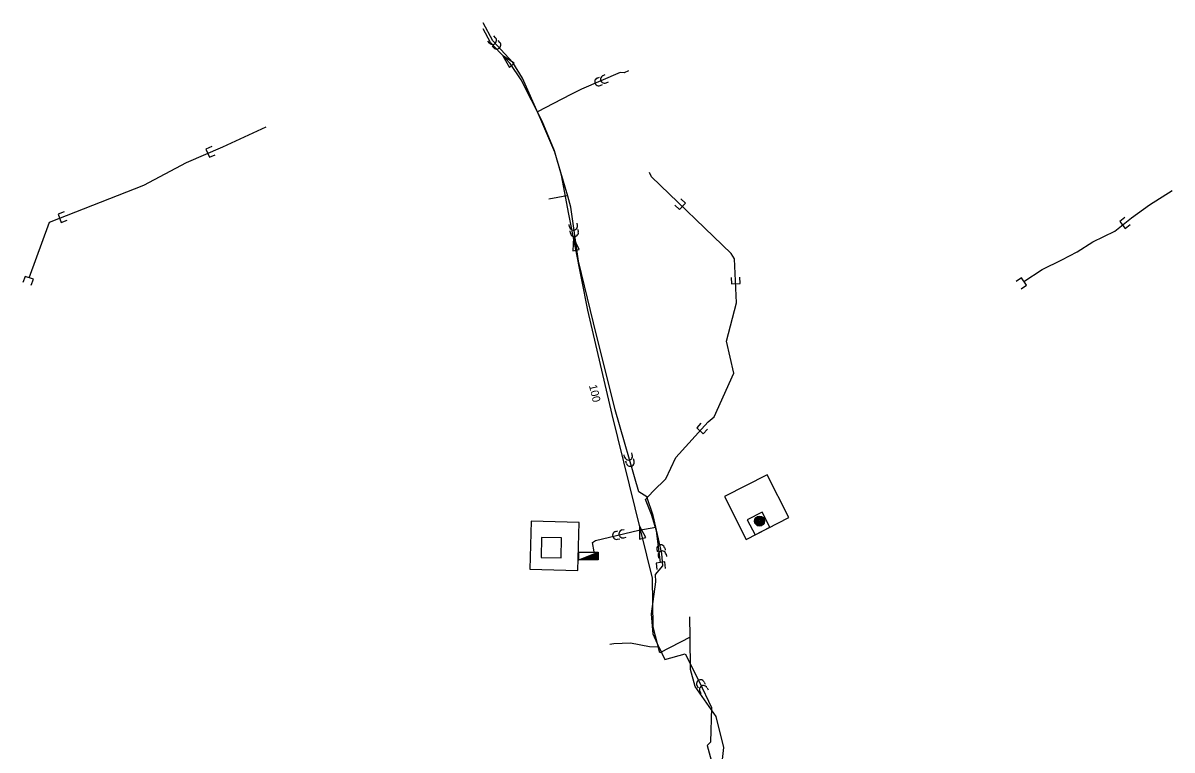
# Model space of a CAD drawing. Extents: x -545007 to -535309, y -1042871 to -1037511.
# Drawn here: x -543287 to -541851, y -1038419 to -1037511 of the extents above; entities that cross this region are included whole.
import ezdxf

# ---------------------------------------------------------------- set-up
doc = ezdxf.new("R2010")
doc.units = 0
for name, color, linetype in [('Vrstva 3', 7, 'Continuous'), ('Vrstva 32', 7, 'Continuous'), ('Vrstva 33', 7, 'Continuous'), ('Vrstva 41', 7, 'Continuous'), ('Vrstva 55', 7, 'Continuous'), ('Vrstva 56', 7, 'Continuous'), ('Vrstva 7', 7, 'Continuous')]:
    doc.layers.add(name, color=color, linetype=linetype)

msp = doc.modelspace()

# ---------------------------------------------------------------- linework, layer by layer
at = {"layer": 'Vrstva 3'}
for points in [[(-542623, -1037670.9), (-542638.2, -1037633.8), (-542664.4, -1037582.1), (-542678.2, -1037561.9), (-542702.7, -1037535.4), (-542712, -1037518.4)], [(-542417.5, -1038472.3), (-542411.5, -1038415.7), (-542420.7, -1038377.1), (-542447.3, -1038339.5), (-542452.8, -1038318.4), (-542453.3, -1038278), (-542491.3, -1038297.4), (-542499.5, -1038265.3), (-542500.4, -1038204.1), (-542550.8, -1037999.9), (-542581.1, -1037869.8), (-542604.9, -1037749.8), (-542614.1, -1037701.3), (-542623, -1037670.9)], [(-542453.3, -1038278), (-542453.7, -1038252.5)]]:
    msp.add_lwpolyline(points, dxfattribs=at)
for points in [[(-542679.2, -1037566.6), (-542673.4, -1037561.2), (-542687.2, -1037552.1)], [(-542599.9, -1037795.5), (-542592.1, -1037793.9), (-542599.1, -1037779)], [(-542516.6, -1038155.4), (-542508.8, -1038153.5), (-542516.5, -1038138.9)]]:
    msp.add_lwpolyline(points, close=True, dxfattribs=at)
at = {"layer": 'Vrstva 32'}
for p, q in [((-542704, -1037536.3), (-542706, -1037534.1)), ((-542696.6, -1037529.6), (-542698.6, -1037527.4)), ((-542691.2, -1037535.4), (-542693.2, -1037533.2)), ((-542698.5, -1037542.2), (-542700.6, -1037540)), ((-542562.2, -1037576.8), (-542559.5, -1037575.6)), ((-542569.6, -1037580), (-542566.8, -1037578.8)), ((-542565.6, -1037589.2), (-542562.9, -1037588)), ((-542558.3, -1037586), (-542555.5, -1037584.8)), ((-542607.4, -1037726.8), (-542629.9, -1037731.1)), ((-542604, -1037765.5), (-542604.4, -1037762.6)), ((-542594.1, -1037764.1), (-542594.5, -1037761.2)), ((-542602.9, -1037773.5), (-542603.3, -1037770.5)), ((-542593, -1037772.1), (-542593.4, -1037769.1)), ((-542535.2, -1038053.3), (-542536, -1038050.4)), ((-542525.6, -1038050.5), (-542526.4, -1038047.7)), ((-542533, -1038061), (-542533.8, -1038058.1)), ((-542523.4, -1038058.2), (-542524.2, -1038055.3)), ((-542546.4, -1038146), (-542543.5, -1038145.3)), ((-542538.6, -1038144.1), (-542535.7, -1038143.5)), ((-542544.1, -1038155.7), (-542541.1, -1038155)), ((-542536.3, -1038153.9), (-542533.4, -1038153.2)), ((-542485.2, -1038166.4), (-542484.6, -1038169.3)), ((-542495, -1038168.6), (-542494.3, -1038171.5)), ((-542493.3, -1038176.4), (-542492.6, -1038179.3)), ((-542483.5, -1038174.2), (-542482.8, -1038177.1)), ((-542444.9, -1038338.4), (-542443.5, -1038341.1)), ((-542436, -1038333.9), (-542434.6, -1038336.5)), ((-542441.2, -1038345.5), (-542439.9, -1038348.2)), ((-542432.3, -1038341), (-542431, -1038343.7))]:
    msp.add_line(p, q, dxfattribs=at)
for points in [[(-542492.6, -1038290), (-542499.4, -1038274.3), (-542501.8, -1038248.7), (-542496.1, -1038209), (-542496.8, -1038199.7), (-542487.4, -1038188.9), (-542488.8, -1038173.3), (-542499.4, -1038125.9), (-542507.4, -1038102.6), (-542517.5, -1038096.7), (-542547, -1037994.2), (-542574.2, -1037885.6), (-542592.9, -1037808.7), (-542602.4, -1037741), (-542606, -1037727.3), (-542622.2, -1037672.3), (-542639.7, -1037631.6), (-542662.7, -1037580.3), (-542674.8, -1037560.6), (-542699.7, -1037533.6), (-542712, -1037511.2)], [(-542530.2, -1037571.1), (-542535.7, -1037573.3), (-542540.6, -1037573), (-542589.2, -1037593.8), (-542602.3, -1037600.4), (-542624.1, -1037611.8), (-542644, -1037622)], [(-542573.1, -1038171.3), (-542575.2, -1038159.8), (-542571.4, -1038157.1), (-542517.4, -1038144.3), (-542496.2, -1038140.4)], [(-542553.9, -1038286.7), (-542548.8, -1038285.7), (-542528, -1038285), (-542504.1, -1038289.5), (-542492.6, -1038290)], [(-542492.6, -1038290), (-542485.1, -1038305.8), (-542459.5, -1038298.6), (-542442, -1038333.1), (-542426.8, -1038365.6), (-542428.1, -1038408.8), (-542432.3, -1038413.3), (-542412.6, -1038485.1)]]:
    msp.add_lwpolyline(points, dxfattribs=at)
for centre, start, end in [((-542700.3, -1037533), 222.6962, 42.6972), ((-542694.9, -1037538.8), 222.6962, 42.6972), ((-542560.3, -1037581.4), 113.2484, 293.2495), ((-542567.6, -1037584.6), 113.2484, 293.2495), ((-542599.1, -1037764.8), 188.0116, 8.0127), ((-542598, -1037772.8), 188.0116, 8.0127), ((-542530.4, -1038051.9), 196.0671, 16.0682), ((-542528.2, -1038059.6), 196.0671, 16.0682), ((-542545.2, -1038150.9), 103.338, 283.3391), ((-542537.4, -1038149), 103.338, 283.3391), ((-542490.1, -1038167.5), 12.5467, 192.5478), ((-542488.4, -1038175.3), 12.5467, 192.5478), ((-542440.4, -1038336.1), 26.975, 206.976), ((-542436.8, -1038343.3), 26.975, 206.976)]:
    msp.add_arc(centre, 5, start, end, dxfattribs=at)
at = {"layer": 'Vrstva 33'}
for points in [[(-543278.9, -1037829.4), (-543253.7, -1037760), (-543135.6, -1037713.5), (-543082.5, -1037685.2), (-543037.3, -1037665.8), (-542982.8, -1037640.7)], [(-543050.9, -1037665.6), (-543058.2, -1037668.8), (-543053.9, -1037678.9), (-543046.5, -1037675.8)], [(-542490.4, -1038184.7), (-542495.3, -1038145.1), (-542501.8, -1038124.8), (-542509.2, -1038106.1), (-542499.6, -1038095.7), (-542483.7, -1038080.1), (-542471.1, -1038053.6), (-542430.9, -1038009.1), (-542423.3, -1038002.8), (-542398.8, -1037948.4), (-542408, -1037908.2), (-542395.3, -1037860.7), (-542397.8, -1037805.5), (-542402.1, -1037799.1), (-542501.5, -1037703.1), (-542504.1, -1037697.9)], [(-542036.5, -1037834.1), (-542013.8, -1037818.8), (-541989, -1037806.7), (-541970.1, -1037797), (-541950.2, -1037784.6), (-541923, -1037770.9), (-541902.1, -1037754.5), (-541879.7, -1037738.3), (-541851.4, -1037720.2)], [(-542472.6, -1037738.7), (-542466.8, -1037744.2), (-542459.2, -1037736.3), (-542465, -1037730.8)], [(-543235.5, -1037746.9), (-543242.9, -1037749.9), (-543238.9, -1037760.1), (-543231.4, -1037757.2)], [(-541910.4, -1037754), (-541916.7, -1037759), (-541909.9, -1037767.6), (-541903.6, -1037762.7)], [(-543276.4, -1037838.7), (-543273.7, -1037831.2), (-543284, -1037827.5), (-543286.8, -1037835)], [(-542402.2, -1037829), (-542401.9, -1037837), (-542390.9, -1037836.5), (-542391.2, -1037828.5)], [(-542040, -1037843.1), (-542033.4, -1037838.6), (-542039.5, -1037829.5), (-542046.2, -1037834)], [(-542439.9, -1038010.8), (-542445.2, -1038016.7), (-542437.1, -1038024.1), (-542431.7, -1038018.1)], [(-542484, -1038192), (-542485, -1038184), (-542495.9, -1038185.4), (-542494.9, -1038193.3)]]:
    msp.add_lwpolyline(points, dxfattribs=at)
at = {"layer": 'Vrstva 41'}
msp.add_lwpolyline([(-542592.6, -1038181.5), (-542592.6, -1038171.9), (-542568.3, -1038171.9)], dxfattribs=at)
for points in [[(-542568.3, -1038171.9), (-542568.3, -1038181.5), (-542592.6, -1038181.5)], [(-542568.9, -1038172.9), (-542568.9, -1038180.9), (-542589.2, -1038180.9)], [(-542569.6, -1038173.8), (-542569.6, -1038180.2), (-542585.9, -1038180.2)], [(-542570.2, -1038174.7), (-542570.2, -1038179.6), (-542582.5, -1038179.6)], [(-542570.8, -1038175.7), (-542570.8, -1038179), (-542579.1, -1038179)], [(-542571.5, -1038176.6), (-542571.5, -1038178.3), (-542575.8, -1038178.3)]]:
    msp.add_lwpolyline(points, close=True, dxfattribs=at)
at = {"layer": 'Vrstva 55'}
for points in [[(-542372.3, -1038150.2), (-542353.8, -1038140.4), (-542363.6, -1038121.8), (-542382.1, -1038131.6), (-542372.3, -1038150.2)], [(-542614.5, -1038178.9), (-542614, -1038153.9), (-542639, -1038153.4), (-542639.5, -1038178.4), (-542614.5, -1038178.9)]]:
    msp.add_lwpolyline(points, dxfattribs=at)
at = {"layer": 'Vrstva 56'}
for points in [[(-542383.4, -1038155.8), (-542329.9, -1038128.6), (-542357.1, -1038075.1), (-542410.6, -1038102.3), (-542383.4, -1038155.8)], [(-542593.8, -1038194.8), (-542592.1, -1038134.8), (-542652.1, -1038133.1), (-542653.8, -1038193.1), (-542593.8, -1038194.8)]]:
    msp.add_lwpolyline(points, dxfattribs=at)
at = {"layer": 'Vrstva 7'}
for radius in [6.3, 5.3, 4.3, 3.3, 2.3, 1.3, 0.3]:
    msp.add_circle((-542366.6, -1038133), radius, dxfattribs=at)

# ---------------------------------------------------------------- texts
at = {"layer": 'Vrstva 3'}
msp.add_text('100', height=10, rotation=283.0891, dxfattribs=at).set_placement((-542579.8, -1037963.7))

doc.saveas('drawing.dxf')
